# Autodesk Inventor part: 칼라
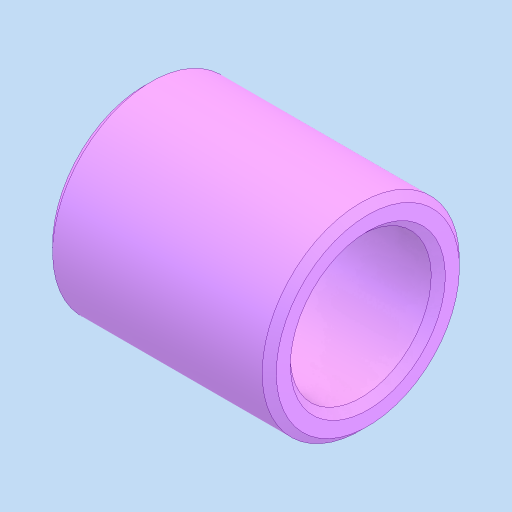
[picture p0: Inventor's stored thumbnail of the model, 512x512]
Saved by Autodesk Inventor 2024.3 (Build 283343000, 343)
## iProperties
Created: 2026-01
Part Number: 칼라
Material: 강철, 연강
Document SubType Name: Modeling
Designer: PC2-02
Density: 7.85 g/cm^3
Appearance: 기본값
Author: jhkim
Sending System: Autodesk Inventor 2026
Preprocessor: ST-DEVELOPER v20.1
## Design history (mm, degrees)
node "칼라1"
node "솔리드2"
node "솔리드1"
